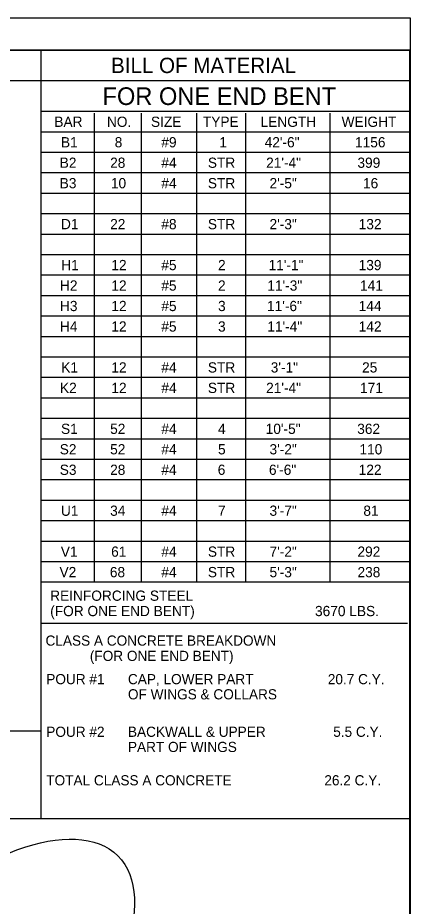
# Model space of a CAD drawing. Extents: x -41 to 191, y -168 to 6.
# Drawn here: x 64.69 to 75.65, y -142.92 to -118.09 of the extents above; entities that cross this region are included whole.
import ezdxf

# ---------------------------------------------------------------- set-up
doc = ezdxf.new("R2010")
doc.units = 0
for name, color, linetype in [('Plan Sheet CELL', 7, 'Continuous'), ('Plot Shape CELL', 7, 'Continuous'), ('Subtitle Text', 7, 'Continuous'), ('Text', 7, 'Continuous'), ('User Information Notes', 7, 'Continuous')]:
    doc.layers.add(name, color=color, linetype=linetype)

msp = doc.modelspace()

# ---------------------------------------------------------------- linework, layer by layer
at = {"layer": 'Plan Sheet CELL'}
for p, q in [((75.648, -118.093), (75.648, -118.093)), ((2.412, -118.994), (75.628, -118.994)), ((75.628, -118.994), (45.504, -118.994)), ((65.332, -118.994), (65.332, -140.465)), ((65.332, -118.994), (65.332, -137.873)), ((75.628, -118.994), (75.628, -137.873)), ((75.628, -118.994), (75.628, -167.042)), ((65.332, -119.853), (49.605, -119.853)), ((75.628, -119.853), (65.332, -119.853)), ((75.628, -120.713), (65.332, -120.713)), ((66.82, -120.756), (66.82, -133.869)), ((68.135, -120.756), (68.135, -133.869)), ((69.68, -120.756), (69.68, -133.869)), ((71.044, -120.756), (71.044, -133.869)), ((73.399, -120.756), (73.399, -133.869)), ((75.628, -121.285), (65.332, -121.285)), ((75.628, -121.857), (65.332, -121.857)), ((75.628, -122.429), (65.332, -122.429)), ((75.628, -123.001), (65.332, -123.001)), ((75.628, -123.573), (65.332, -123.573)), ((75.628, -124.145), (65.332, -124.145)), ((75.628, -124.717), (65.332, -124.717)), ((75.628, -125.289), (65.332, -125.289)), ((75.628, -125.861), (65.332, -125.861)), ((75.628, -126.433), (65.332, -126.433)), ((75.628, -127.005), (65.332, -127.005)), ((75.628, -127.577), (65.332, -127.577)), ((75.628, -128.149), (65.332, -128.149)), ((75.628, -128.721), (65.332, -128.721)), ((75.628, -129.293), (65.332, -129.293)), ((75.628, -129.865), (65.332, -129.865)), ((75.628, -130.437), (65.332, -130.437)), ((75.628, -131.009), (65.332, -131.009)), ((75.628, -131.581), (65.332, -131.581)), ((75.628, -132.153), (65.332, -132.153)), ((75.628, -132.725), (65.332, -132.725)), ((75.628, -133.297), (65.332, -133.297)), ((75.628, -133.869), (65.332, -133.869)), ((65.332, -135.013), (75.577, -135.013)), ((49.605, -138.022), (65.332, -138.022)), ((49.605, -140.465), (75.628, -140.465))]:
    msp.add_line(p, q, dxfattribs=at)
at = {"layer": 'Plot Shape CELL'}
msp.add_lwpolyline([(0, -118.093), (75.648, -118.093), (75.648, -168.429), (0, -168.429)], close=True, dxfattribs=at)
at = {"layer": 'User Information Notes'}
msp.add_ellipse((62.956, -146.039), major_axis=(4.526, 4.526), ratio=0.46622, dxfattribs=at)

# ---------------------------------------------------------------- texts
at = {"layer": 'Subtitle Text'}
for s, height, p in [('BILL OF MATERIAL', 0.429, (67.294, -119.638)), ('FOR ONE END BENT', 0.49335, (67.055, -120.53))]:
    msp.add_text(s, height=height, dxfattribs=at).set_placement(p)
at = {"layer": 'Text'}
for s, height, p in [('BAR', 0.286, (65.71, -121.142)), ('NO.', 0.286, (67.178, -121.142)), ('SIZE', 0.286, (68.408, -121.142)), ('TYPE', 0.286, (69.859, -121.142)), ('LENGTH', 0.286, (71.469, -121.142)), ('WEIGHT', 0.286, (73.732, -121.142)), ('B1', 0.286, (65.895, -121.714)), ('8', 0.286, (67.396, -121.714)), ('#9', 0.286, (68.697, -121.714)), ('1', 0.286, (70.317, -121.714)), ('42\'-6"', 0.286, (71.583, -121.714)), ('1156', 0.286, (74.107, -121.714)), ('B2', 0.286, (65.859, -122.286)), ('28', 0.286, (67.268, -122.286)), ('#4', 0.286, (68.698, -122.286)), ('STR', 0.286, (69.997, -122.286)), ('21\'-4"', 0.286, (71.624, -122.286)), ('399', 0.286, (74.174, -122.286)), ('B3', 0.286, (65.859, -122.858)), ('10', 0.286, (67.289, -122.858)), ('#4', 0.286, (68.698, -122.858)), ('STR', 0.286, (69.997, -122.858)), ('2\'-5"', 0.286, (71.719, -122.858)), ('16', 0.286, (74.33, -122.858)), ('D1', 0.286, (65.895, -124.002)), ('22', 0.286, (67.268, -124.002)), ('#8', 0.286, (68.698, -124.002)), ('STR', 0.286, (69.997, -124.002)), ('2\'-3"', 0.286, (71.719, -124.002)), ('132', 0.286, (74.21, -124.002)), ('H1', 0.286, (65.903, -125.146)), ('12', 0.286, (67.302, -125.146)), ('#5', 0.286, (68.698, -125.146)), ('2', 0.286, (70.281, -125.146)), ('11\'-1"', 0.286, (71.692, -125.146)), ('139', 0.286, (74.208, -125.146)), ('H2', 0.286, (65.867, -125.718)), ('12', 0.286, (67.302, -125.718)), ('#5', 0.286, (68.698, -125.718)), ('2', 0.286, (70.281, -125.718)), ('11\'-3"', 0.286, (71.658, -125.718)), ('141', 0.286, (74.246, -125.718)), ('H3', 0.286, (65.867, -126.29)), ('12', 0.286, (67.302, -126.29)), ('#5', 0.286, (68.698, -126.29)), ('3', 0.286, (70.281, -126.29)), ('11\'-6"', 0.286, (71.65, -126.29)), ('144', 0.286, (74.21, -126.29)), ('H4', 0.286, (65.867, -126.862)), ('12', 0.286, (67.302, -126.862)), ('#5', 0.286, (68.698, -126.862)), ('3', 0.286, (70.281, -126.862)), ('11\'-4"', 0.286, (71.658, -126.862)), ('142', 0.286, (74.21, -126.862)), ('K1', 0.286, (65.903, -128.006)), ('12', 0.286, (67.302, -128.006)), ('#4', 0.286, (68.698, -128.006)), ('STR', 0.286, (69.997, -128.006)), ('3\'-1"', 0.286, (71.753, -128.006)), ('25', 0.286, (74.304, -128.006)), ('K2', 0.286, (65.867, -128.578)), ('12', 0.286, (67.302, -128.578)), ('#4', 0.286, (68.698, -128.578)), ('STR', 0.286, (69.997, -128.578)), ('21\'-4"', 0.286, (71.624, -128.578)), ('171', 0.286, (74.246, -128.578)), ('S1', 0.286, (65.896, -129.722)), ('52', 0.286, (67.268, -129.722)), ('#4', 0.286, (68.698, -129.722)), ('4', 0.286, (70.281, -129.722)), ('10\'-5"', 0.286, (71.612, -129.722)), ('362', 0.286, (74.168, -129.722)), ('S2', 0.286, (65.86, -130.294)), ('52', 0.286, (67.268, -130.294)), ('#4', 0.286, (68.698, -130.294)), ('5', 0.286, (70.281, -130.294)), ('3\'-2"', 0.286, (71.719, -130.294)), ('110', 0.286, (74.231, -130.294)), ('S3', 0.286, (65.86, -130.866)), ('28', 0.286, (67.268, -130.866)), ('#4', 0.286, (68.698, -130.866)), ('6', 0.286, (70.273, -130.866)), ('6\'-6"', 0.286, (71.703, -130.866)), ('122', 0.286, (74.21, -130.866)), ('U1', 0.286, (65.894, -132.01)), ('34', 0.286, (67.268, -132.01)), ('#4', 0.286, (68.698, -132.01)), ('7', 0.286, (70.281, -132.01)), ('3\'-7"', 0.286, (71.719, -132.01)), ('81', 0.286, (74.34, -132.01)), ('V1', 0.286, (65.89, -133.154)), ('61', 0.286, (67.296, -133.154)), ('#4', 0.286, (68.698, -133.154)), ('STR', 0.286, (69.997, -133.154)), ('7\'-2"', 0.286, (71.719, -133.154)), ('292', 0.286, (74.175, -133.154)), ('V2', 0.286, (65.854, -133.726)), ('68', 0.286, (67.26, -133.726)), ('#4', 0.286, (68.698, -133.726)), ('STR', 0.286, (69.997, -133.726)), ('5\'-3"', 0.286, (71.719, -133.726)), ('238', 0.286, (74.176, -133.726)), ('REINFORCING STEEL', 0.286, (65.594, -134.385)), ('(FOR ONE END BENT)', 0.286, (65.594, -134.814)), ('3670 LBS.', 0.286, (72.99, -134.814)), ('CLASS A CONCRETE BREAKDOWN', 0.28433, (65.463, -135.639)), ('(FOR ONE END BENT)', 0.28433, (66.701, -136.066)), ('POUR #1', 0.2843, (65.484, -136.716)), ('CAP, LOWER PART', 0.28433, (67.765, -136.716)), ('20.7 C.Y.', 0.2843, (73.347, -136.716)), ('OF WINGS & COLLARS', 0.28433, (67.765, -137.14)), ('POUR #2', 0.2843, (65.484, -138.187)), ('BACKWALL & UPPER', 0.28433, (67.765, -138.187)), ('5.5 C.Y.', 0.2843, (73.498, -138.187)), ('PART OF WINGS', 0.28433, (67.765, -138.611)), ('TOTAL CLASS A CONCRETE', 0.28433, (65.484, -139.543)), ('26.2 C.Y.', 0.2843, (73.25, -139.543))]:
    msp.add_text(s, height=height, dxfattribs=at).set_placement(p)

doc.saveas('drawing.dxf')
